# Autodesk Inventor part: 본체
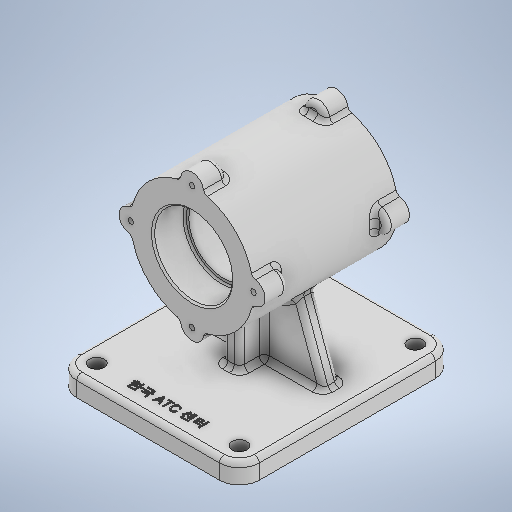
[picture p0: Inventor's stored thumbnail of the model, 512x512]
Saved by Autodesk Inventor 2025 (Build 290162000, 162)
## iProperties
Created: 2024-08
Part Number: 본체
Material: 일반
Document SubType Name: Modeling
Designer: deana
Density: 1 g/cm^3
Appearance: 기본값
Mass: 435.956 g
Surface Area: 772.832 cm^2
Volume: 435.956 cm^3
Author: deana
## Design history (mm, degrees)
sketch "스케치1"
  geometry: L1 (43, -60)-(-43, -60); L2 (-55, -48)-(-55, 58); L3 (-43, 70)-(43, 70); L4 (55, 58)-(55, -48); L5 (55, -60)-(-55, 70); L6 (-55, -60)-(55, 70); A1 r 12 centre (43, -48) between (43, -60) and (55, -48); A2 r 12 centre (-43, -48) between (-55, -48) and (-43, -60); A3 r 12 centre (-43, 58) between (-43, 70) and (-55, 58); A4 r 12 centre (43, 58) between (55, 58) and (43, 70); 2 further points
  constraints: 12 end point, 8 point on circle, 8 point on line, 8 tangent, 4 centre point, 3 equal radius, 2 midpoint, 2 parallel, 1 horizontal, 1 perpendicular, 1 vertical alignment
  dimensions: "d0" = 110 distance of L5.end L6.end; "d1" = 130 distance of L6.start L5.end; "d2" = 12 radius of A1; "d42" = 5 distance of point (0, 0) point (0, 5); "d43" = 70 distance from line of L3 point (0, 0) (derived)
extrude "돌출1" new body sketch "스케치1" distance "d3" = 12; taper "d4" = 0 deg
sketch "스케치2"
  geometry: C1 r 37 at (0, 82); 1 further point
  constraints: 1 centre point, 1 vertical alignment
  dimensions: "d5" = 74 diameter of C1; "d6" = 82 distance of point (0, 0) C1.centre
extrude "돌출2" join sketch "스케치2" stored distance "d7" = 87; taper "d8" = 0 deg
sketch "스케치3"
  geometry: C1 r 7 at (0, 37); 2 further points
  constraints: 2 vertical alignment, 1 centre point, 1 other
  dimensions: "d9" = 14 diameter of C1
extrude "돌출3" join sketch "스케치3" distance "d10" = 14; taper "d11" = 0 deg
sketch "스케치4"
  geometry: A1 r 7 centre (0, 119) between (6.969, 118.338) and (-6.969, 118.338) reference; 2 further points
  constraints: 1 coincident
hole "구멍1" sketch "스케치4" at (0, 119) diameter "d12" = 3.242; stored, may be unused: countersink angle "d16" = 90 deg, drill point angle "d18" = 120 deg; dims "d13" = 8, "d14" = 4, "d15" = 2, "d17" = 10
fillet "모깎기1" dims "d19" = 3
fillet "모깎기2" dims "d20" = 3
sketch "스케치5"
  geometry: L1 (0, 119.152)-(0, 12); L2 (0, 12)-(41, 12); L3 (41, 12)-(15.124, 83.092); L4 (43, 12)-(-43, 12) reference; L5 (55, 12)-(43, 12) reference; L6 (-41, 12)-(-11.124, 83.092); L7 (0, 12)-(-41, 12); L8 (-43, 0)-(43, 0) reference; L9 (55, 0)-(55, 12) reference; L10 (-11.124, 83.092)-(15.124, 83.092); 6 further points
  constraints: 12 end point, 1 horizontal, 1 horizontal alignment, 1 midpoint, 1 perpendicular, 1 symmetric about line, 1 vertical, 1 vertical alignment
  dimensions: "d25" = 110 deg angle of L5 L3; "d26" = 14 distance of L5.start L2.end; "d29" = 26.24893 distance of L3.end L6.end; "d30" = 71.09245 vertical distance of L6.start L6.end
extrude "돌출4" join sketch "스케치5" stored distance "d27" = 10; taper "d28" = 0 deg
sketch "스케치7"
  geometry: L1 (4.473, 20)-(81.429, 20); L2 (81.429, 20)-(81.429, -20); L3 (81.429, -20)-(4.473, -20); L4 (4.473, -20)-(4.473, 20); L5 (4.473, 20)-(81.429, -20); L6 (81.429, 20)-(4.473, -20); L7 (0, 70)-(12, 70) reference; 4 further points
  constraints: 12 end point, 4 midpoint, 2 parallel, 1 horizontal, 1 perpendicular
  dimensions: "d36" = 40 distance of L2.end L1.end; "d37" = 50 vertical distance of point (6, 70) point (42.951, 20); "d38" = 76.95648 distance of L2.end L3.end; "d39" = 4.47297 horizontal distance of point (0, 0) L3.end
extrude "돌출6" join sketch "스케치7" stored distance "d44" = 10; taper "d45" = 0 deg
fillet "모깎기3" dims "d46" = 3
fillet "모깎기4" dims "d47" = 3
fillet "모깎기5" dims "d48" = 3
fillet "모깎기6" dims "d56" = 3
sketch "스케치9"
  geometry: L1 (-43, -70)-(43, -70) reference; 2 further points
  constraints: 1 vertical alignment, 1 other
  dimensions: "d58" = 58 distance of point (0, 0) point (0, -58)
feature "엠보싱1" sketch "스케치9" dims "d61" = 0.5, "d62" = 0
sketch "스케치10"
  geometry: L1 (82, 43.5)-(105.5, 43.5); L2 (105.5, 43.5)-(105.5, 25.5); L3 (104.5, 24.5)-(103, 24.5); L4 (103, 24.5)-(103, 0); L5 (103, 0)-(105.879, 0); L6 (103, -24.5)-(103, 0); L7 (104.5, -24.5)-(103, -24.5); L8 (105.5, -43.5)-(105.5, -25.5); L9 (82, -43.5)-(105.5, -43.5); L10 (82, 43.5)-(82, -43.5); L11 (82, 43.5)-(82, 56.947); L12 (0, 70)-(9, 70) reference; A1 r 1 centre (104.5, 25.5) between (104.5, 24.5) and (105.5, 25.5); A2 r 1 centre (104.5, -25.5) between (105.5, -25.5) and (104.5, -24.5); 4 further points
  constraints: 22 end point, 4 point on circle, 4 point on line, 4 symmetric about line, 4 tangent, 3 perpendicular, 2 centre point, 2 horizontal, 2 vertical, 1 equal radius, 1 midpoint
  dimensions: "d63" = 87 distance of L8.start L1.end; "d64" = 19 distance of L1.end point (105.5, 24.5); "d65" = 47 diameter of L1.end L11; "d66" = 42 diameter of L3.end L11; "d67" = 1 radius of A1; "d68" = 70 vertical distance of L12.end point (82, 0); "d69" = 82 distance of point (0, 0) point (82, 0)
revolve "회전1" sketch "스케치10" stored, may be unused: angle "d70" = 90 deg
chamfer "모따기1" distance "d71" = 1; stored, may be unused: second distance "d72" = 2, angle "d73" = 45 deg
sketch "스케치11"
  geometry: L1 (-43, 48)-(43, 48); L2 (43, 48)-(43, -58); L3 (43, -58)-(-43, -58); L4 (-43, -58)-(-43, 48); L5 (-43, 48)-(43, -58); L6 (43, 48)-(-43, -58); L7 (-43, -70)-(43, -70) reference; 2 further points
  constraints: 12 end point, 2 midpoint, 2 parallel, 1 horizontal, 1 perpendicular, 1 vertical alignment
  dimensions: "d75" = 86 distance of L2.end L3.end; "d76" = 106 distance of L1.end L2.end; "d77" = 12 distance from line of L7 L2.end
hole "구멍3" sketch "스케치11" at (-43, -58), (43, -58), (43, 48), (-43, 48) diameter "d78" = 9; stored, may be unused: countersink angle "d82" = 90 deg, drill point angle "d84" = 0 deg; dims "d79" = 6, "d80" = 4, "d81" = 2, "d83" = 15
node "솔리드1"
pattern_circular "원형 패턴1" dims "d22" = 360 deg
mirror "미러1"
feature "A9D066F2-1C7D-4E18-AEED-F7BC21143FA4" dims "d78" = 9, "d79" = 6, "d80" = 4, "d81" = 2, "d82" = 90 deg, "d83" = 15, "d84" = 0
